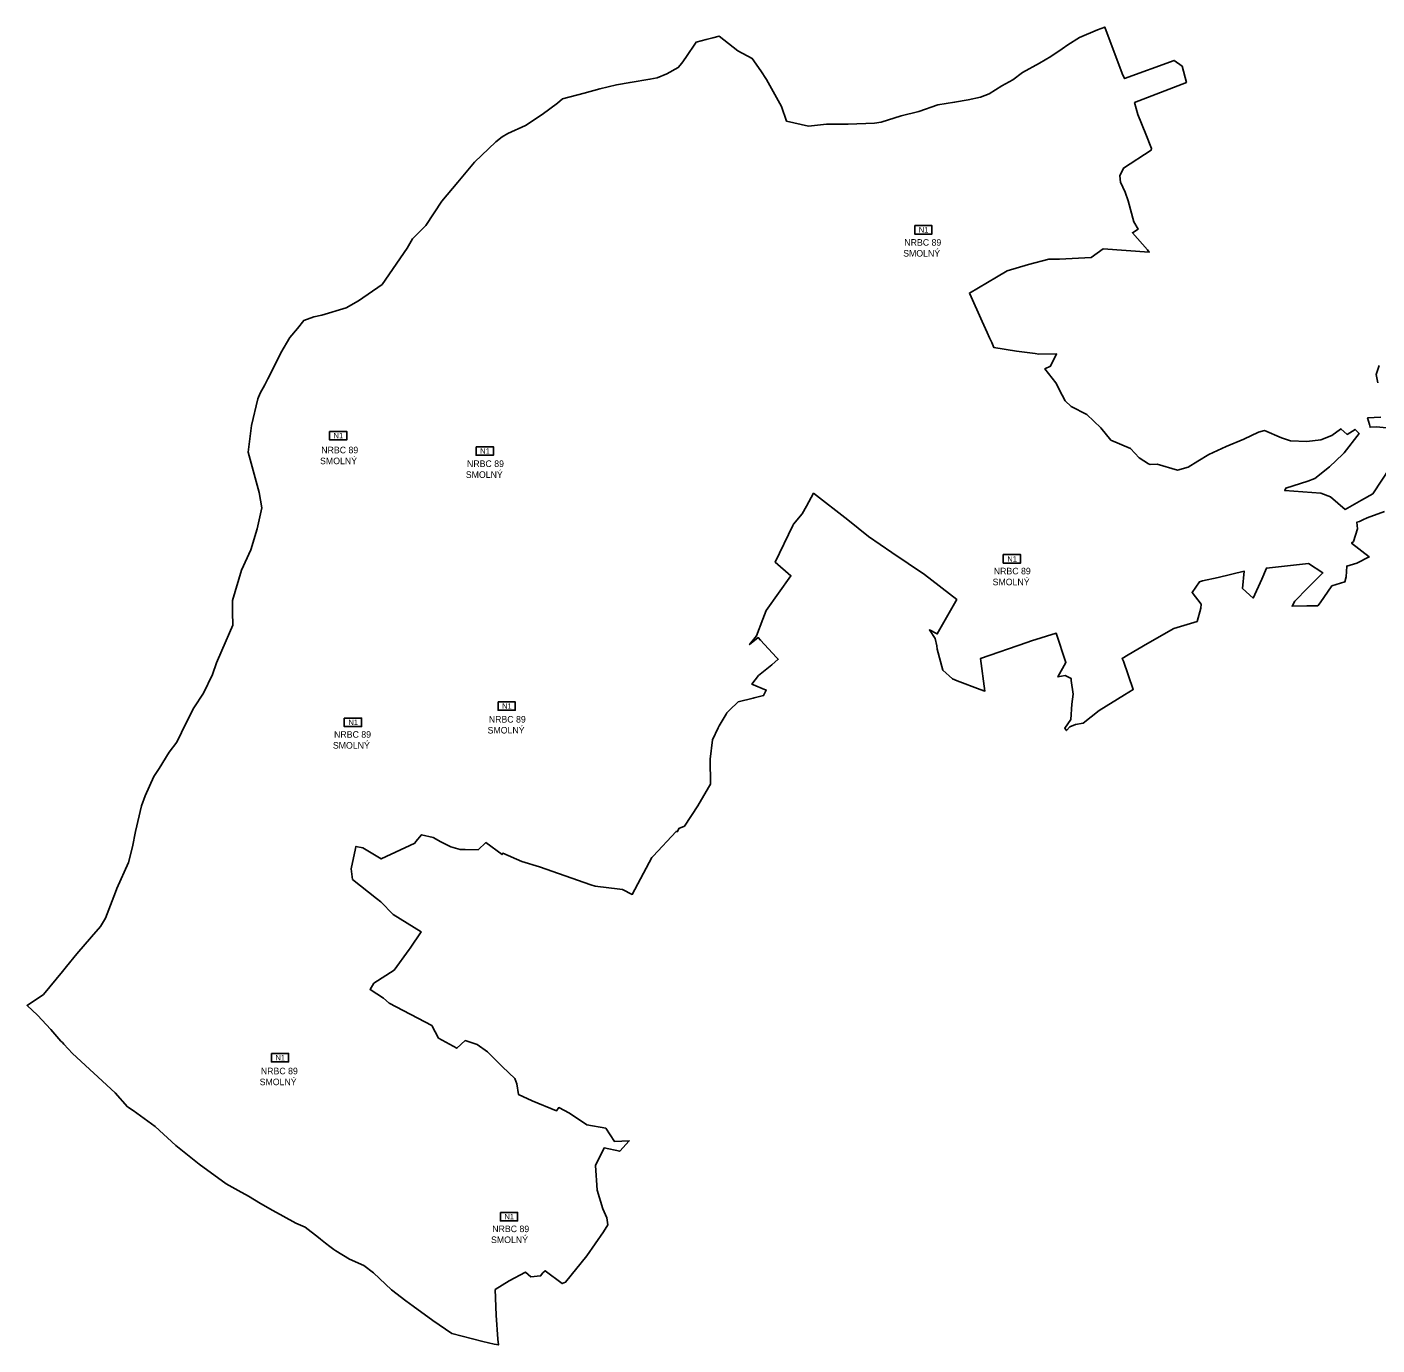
# Model space of a CAD drawing. Extents: x -546680 to -530218, y -1046521 to -1035695.
# Drawn here: x -545342 to -542866, y -1040078 to -1037661 of the extents above; entities that cross this region are included whole.
import ezdxf

# ---------------------------------------------------------------- set-up
doc = ezdxf.new("R2010")
doc.units = 0
for name, color, linetype in [('Vrstva 18', 7, 'Continuous'), ('Vrstva 3', 7, 'Continuous'), ('Vrstva 30', 7, 'Continuous'), ('Vrstva 82', 7, 'Continuous')]:
    doc.layers.add(name, color=color, linetype=linetype)

msp = doc.modelspace()

# ---------------------------------------------------------------- linework, layer by layer
at = {"layer": 'Vrstva 18'}
for points in [[(-542842.2, -1038469), (-542873.9, -1038517.1), (-542894.6, -1038529), (-542924.4, -1038545.8), (-542951.6, -1038523), (-542969.1, -1038516), (-543035.3, -1038511.4), (-543033.5, -1038506.9), (-542992.8, -1038494.1), (-542980.1, -1038489), (-542953.4, -1038468.1), (-542928.9, -1038444.7), (-542926.5, -1038442.1), (-542899, -1038406.7), (-542901.8, -1038403.8), (-542906.3, -1038399.3), (-542920.5, -1038408.5), (-542932.3, -1038398.1), (-542933.2, -1038398.7), (-542948.7, -1038410.6), (-542969.2, -1038418.6), (-542994.7, -1038421.2), (-543024.4, -1038419.9), (-543041.4, -1038414.9), (-543072.2, -1038401.5), (-543083.1, -1038404.1), (-543110.6, -1038417.1), (-543142.5, -1038430.5), (-543174.7, -1038445.5), (-543194.6, -1038457.3), (-543212.2, -1038468.2), (-543231.8, -1038473.9), (-543269.5, -1038462.9), (-543281.9, -1038463.3), (-543285, -1038462.5), (-543302.5, -1038451.6), (-543318, -1038434.2), (-543354.2, -1038418.9), (-543372.8, -1038396.3), (-543398, -1038371.7), (-543427, -1038357), (-543437.7, -1038346.5), (-543443.6, -1038336.6), (-543455.2, -1038313.8), (-543468.8, -1038296.4), (-543475, -1038287.9), (-543464.8, -1038283.2), (-543453.8, -1038260.9), (-543486.1, -1038261.1), (-543493.2, -1038260.1), (-543527.1, -1038255.8), (-543568.9, -1038248.7), (-543572.8, -1038240), (-543576.7, -1038231.1), (-543580.9, -1038221.6), (-543590, -1038201.2), (-543612.8, -1038150.6), (-543613.5, -1038149.1), (-543563.7, -1038120), (-543544.4, -1038108.5), (-543505.3, -1038096.8), (-543467.8, -1038086.7), (-543448.1, -1038086.9), (-543390.5, -1038084), (-543368.1, -1038067.8), (-543283.7, -1038074), (-543287.1, -1038070), (-543314.8, -1038038.5), (-543304.2, -1038032), (-543311.9, -1038018.7), (-543322.7, -1037980), (-543327.7, -1037964.2), (-543336.6, -1037945.7), (-543337.9, -1037933.9), (-543330.9, -1037919.8), (-543280.3, -1037887.3), (-543279.4, -1037884.1), (-543290.1, -1037857.8), (-543304.7, -1037821.8), (-543310.7, -1037799.9), (-543215.6, -1037763.1), (-543223.5, -1037733.1), (-543237.9, -1037722.6), (-543329, -1037755.8), (-543333.7, -1037746.3), (-543365.3, -1037661.2), (-543378.7, -1037666.2), (-543411.7, -1037680.3), (-543433.4, -1037694.1), (-543443.8, -1037701.3), (-543464.1, -1037715.4), (-543485.3, -1037727.6), (-543516.1, -1037744.8), (-543533.8, -1037757.8), (-543554.4, -1037769.2), (-543577.4, -1037784), (-543593.1, -1037789.8), (-543615.7, -1037794.6), (-543640.7, -1037799.2), (-543671.3, -1037804.1), (-543706.6, -1037816.2), (-543738.5, -1037824.2), (-543775.7, -1037835.8), (-543787.8, -1037837.8), (-543836.2, -1037839.6), (-543864.7, -1037839.4), (-543875.7, -1037839.6), (-543908.9, -1037842.9), (-543949.2, -1037833.6), (-543958.1, -1037807.2), (-543985.5, -1037757.2), (-543995.9, -1037741.3), (-544012, -1037718.9), (-544038.2, -1037704.7), (-544072.3, -1037678), (-544084.2, -1037681.2), (-544086.4, -1037681.7), (-544096.2, -1037684.3), (-544114.8, -1037689.2), (-544133.5, -1037717.2), (-544141, -1037727.7), (-544147.8, -1037735.5), (-544168.3, -1037747), (-544186.4, -1037754.7), (-544199.6, -1037757.1), (-544235.9, -1037762.7), (-544260.7, -1037767.4), (-544291.6, -1037774.5), (-544320.1, -1037782.7), (-544359.9, -1037792.8), (-544368.9, -1037801.1), (-544397.5, -1037821.5), (-544427.6, -1037842), (-544460.2, -1037856.7), (-544470.8, -1037862.4), (-544482.1, -1037871.9), (-544521.4, -1037909), (-544552.2, -1037945.7), (-544581.4, -1037980.8), (-544610.5, -1038025.1), (-544635, -1038049.6), (-544644.7, -1038066.8), (-544690.5, -1038133.3), (-544733.9, -1038163.3), (-544756.8, -1038176.3), (-544801.6, -1038189.5), (-544815.9, -1038192.9), (-544834.5, -1038199.3), (-544846.1, -1038214.3), (-544860, -1038230.9), (-544876.4, -1038258.7), (-544896.9, -1038299.8), (-544900.3, -1038306.4), (-544905.9, -1038317.4), (-544914.6, -1038332.8), (-544918.7, -1038343), (-544930.4, -1038392.2), (-544936.4, -1038440.7), (-544916.2, -1038514.7), (-544911.5, -1038543), (-544919.8, -1038581.8), (-544931.3, -1038620.2), (-544948.5, -1038657.6), (-544965.5, -1038713.1), (-544965.4, -1038734.1), (-544964.4, -1038758.3), (-544984.5, -1038804.7), (-544994.6, -1038827.5), (-545002, -1038848.8), (-545018.4, -1038882.7), (-545036, -1038909.9), (-545050.2, -1038937.3), (-545067.3, -1038972.6), (-545081.3, -1038991.1), (-545099.8, -1039020.9), (-545109.7, -1039035.5), (-545125.5, -1039071.5), (-545132.3, -1039089.8), (-545143.1, -1039136.7), (-545148.6, -1039164.9), (-545156.2, -1039193.4), (-545177.5, -1039241.2), (-545179.6, -1039247.7), (-545198.3, -1039295.8), (-545207.2, -1039311.1), (-545223.7, -1039329.9), (-545250.7, -1039361.1), (-545269.4, -1039384.5), (-545277.1, -1039393.5), (-545311.8, -1039435.4), (-545342.1, -1039455.5), (-545323.1, -1039473.5), (-545298.5, -1039500), (-545279.9, -1039520.9), (-545277.3, -1039523.9), (-545274.8, -1039526.7), (-545258.9, -1039543.8), (-545180.4, -1039616), (-545158.1, -1039641.5), (-545147.7, -1039648.1), (-545107.2, -1039677.4), (-545069.2, -1039712.3), (-545026.5, -1039747), (-544977.1, -1039782.6), (-544954.9, -1039795), (-544935.7, -1039805.6), (-544914, -1039818.7), (-544891.2, -1039831.7), (-544872.1, -1039842.3), (-544849.3, -1039854.8), (-544832, -1039862.5), (-544807.7, -1039881.4), (-544803.6, -1039884.5), (-544794.5, -1039891.6), (-544792.3, -1039893.2), (-544791.9, -1039893.6), (-544789, -1039895.8)], [(-542862.1, -1038281.8), (-542867.4, -1038298.6), (-542864.8, -1038313.5)], [(-542859.1, -1038376.6), (-542883.4, -1038378), (-542880, -1038390.4), (-542878.7, -1038395.2), (-542867.8, -1038394.6), (-542847.8, -1038396.5)], [(-544483.5, -1039976.4), (-544457.7, -1039961), (-544427.8, -1039945.1), (-544417.9, -1039953.1), (-544400, -1039951.6), (-544396.3, -1039946.3), (-544391.5, -1039942.2), (-544360.4, -1039965.7), (-544354.4, -1039963.2), (-544315.6, -1039914.8), (-544284.8, -1039870.8), (-544276.8, -1039858.3), (-544278.9, -1039845.1), (-544286.1, -1039828.4), (-544296.2, -1039794.7), (-544299.3, -1039749.2), (-544283.7, -1039716.8), (-544255.1, -1039723.1), (-544237.6, -1039704.1), (-544264.6, -1039705.1), (-544280.7, -1039680.6), (-544315.1, -1039674.7), (-544347.3, -1039653.1), (-544366.9, -1039643.1), (-544370.8, -1039648.7), (-544415.8, -1039630.9), (-544440.8, -1039618.8), (-544443.6, -1039599.7), (-544447.2, -1039589.8), (-544469.7, -1039568.1), (-544497.3, -1039540.7), (-544516.6, -1039527.5), (-544538.2, -1039520.2), (-544553.5, -1039534.2), (-544587.3, -1039515.6), (-544599.9, -1039492.4), (-544678.1, -1039451.3), (-544688.2, -1039442.1), (-544712.9, -1039426.7), (-544706.2, -1039415), (-544668.8, -1039391), (-544641.2, -1039353.1), (-544639.4, -1039350.6), (-544618.9, -1039320.7), (-544670.8, -1039288.9), (-544693.2, -1039265.8), (-544701.1, -1039259.5), (-544745, -1039224.6), (-544747.3, -1039205.4), (-544739.5, -1039167.7), (-544738.8, -1039163.9), (-544726.4, -1039166.3), (-544692.3, -1039187), (-544630.9, -1039158), (-544628.7, -1039155.2), (-544618.6, -1039142.6), (-544597.3, -1039147.8), (-544582.8, -1039155.3), (-544564.5, -1039164.8), (-544547.4, -1039169.8), (-544538.5, -1039169.8), (-544514.8, -1039170.1), (-544500.7, -1039156.9), (-544470.7, -1039179), (-544469.4, -1039176.4), (-544434.5, -1039191.7), (-544402.4, -1039201.7), (-544307.8, -1039234.6), (-544300.1, -1039236.8), (-544254.5, -1039242.2), (-544249.8, -1039242.8), (-544231.9, -1039251.9), (-544195.8, -1039184.6), (-544193.8, -1039181.7), (-544151.7, -1039136.6), (-544148.8, -1039136.8), (-544146.8, -1039131.4), (-544136.4, -1039126.7), (-544111.5, -1039089.6), (-544092.2, -1039056), (-544088.6, -1039049.8), (-544089.3, -1039004), (-544085, -1038968.5), (-544074.5, -1038946.6), (-544072.6, -1038942.6), (-544059.7, -1038921.2), (-544058.4, -1038918.9), (-544053.4, -1038914.1), (-544037.6, -1038898.9), (-544010.5, -1038892.2), (-544008.6, -1038891.8), (-543991.1, -1038887.5), (-543986.1, -1038877.4), (-544012.5, -1038866.5), (-544000.4, -1038850.3), (-543976.1, -1038830.8), (-543964.3, -1038820.8), (-543967.5, -1038817.5), (-543996.6, -1038785.8), (-544001, -1038781.1), (-544016.7, -1038793.7), (-544004, -1038777.8), (-543992.4, -1038747.4), (-543986.3, -1038731.5), (-543940.9, -1038667.7), (-543970, -1038642.4), (-543937.5, -1038575.3), (-543936.4, -1038573.1), (-543920.2, -1038553.8), (-543912.3, -1038539.7), (-543899.4, -1038516.3), (-543836.9, -1038564.8), (-543798.7, -1038595.6), (-543756.2, -1038625), (-543696.1, -1038665.2), (-543636.7, -1038711.2), (-543638.3, -1038714.1), (-543672.6, -1038774.4), (-543687, -1038766.8), (-543676.4, -1038782.8), (-543673.4, -1038795.9), (-543672.6, -1038802.5), (-543662.4, -1038841), (-543644.6, -1038856.9), (-543636.2, -1038860.1), (-543594, -1038876.2), (-543585.2, -1038879), (-543593, -1038819.2), (-543508.1, -1038790), (-543499.8, -1038787.2), (-543454.4, -1038773), (-543436.5, -1038826.7), (-543451.3, -1038853.2), (-543438.1, -1038850.8), (-543427, -1038856), (-543426.8, -1038859.6), (-543423.3, -1038885), (-543425.6, -1038903.1), (-543427.4, -1038931.3), (-543438.8, -1038947.2), (-543435.3, -1038951.5), (-543429.3, -1038944.8), (-543418.9, -1038940.5), (-543405, -1038938), (-543375.7, -1038914.8), (-543329.1, -1038885.9), (-543313, -1038876.3), (-543331.2, -1038824.5), (-543333.7, -1038819.2), (-543322.6, -1038812.8), (-543286.7, -1038792), (-543238.8, -1038764.6), (-543195.9, -1038751.5), (-543188.9, -1038727.1), (-543188.8, -1038720), (-543205.3, -1038698.2), (-543191.8, -1038679), (-543186.4, -1038677.2), (-543157.6, -1038670.6), (-543109.5, -1038659.2), (-543112.6, -1038690.9), (-543093.3, -1038708.7), (-543077.5, -1038673.9), (-543068.9, -1038653.5), (-542991.5, -1038645.4), (-542965.1, -1038662.3), (-542992.7, -1038690), (-543016.9, -1038714.3), (-543021.8, -1038723.6), (-542994.6, -1038722.6), (-542974.6, -1038722.7), (-542970.5, -1038717.2), (-542948.8, -1038686), (-542925.2, -1038678.8), (-542922.8, -1038669.5), (-542921.6, -1038649.8), (-542903.3, -1038644.4), (-542880.2, -1038633), (-542912.7, -1038607.6), (-542909.3, -1038604.6), (-542901.7, -1038581.6), (-542902.8, -1038569.2), (-542898.4, -1038568.4), (-542891.9, -1038565.2), (-542884.3, -1038561.6), (-542852.6, -1038549.6)], [(-544789, -1039895.8), (-544779.3, -1039903.3), (-544775.9, -1039905.9), (-544750.7, -1039920.8), (-544724.3, -1039932.5), (-544706.7, -1039945.8), (-544673.4, -1039977.3), (-544647.1, -1039997.5), (-544634, -1040007.1), (-544597.7, -1040033.6), (-544563.2, -1040057.3), (-544506.2, -1040072)], [(-544478.4, -1040067.8), (-544481.5, -1040023.9), (-544483.5, -1039976.4)], [(-544506.2, -1040072), (-544485.4, -1040076.6), (-544480.7, -1040077.7), (-544477.6, -1040078.4), (-544478.4, -1040067.8)]]:
    msp.add_lwpolyline(points, dxfattribs=at)
at = {"layer": 'Vrstva 30'}
for points in [[(-543714, -1038025.4), (-543714, -1038040.9), (-543682.3, -1038040.9), (-543682.3, -1038025.4), (-543714, -1038025.4)], [(-544787.3, -1038402.9), (-544787.3, -1038418.4), (-544755.6, -1038418.4), (-544755.6, -1038402.9), (-544787.3, -1038402.9)], [(-544518.3, -1038431.1), (-544518.3, -1038446.6), (-544486.6, -1038446.6), (-544486.6, -1038431.1), (-544518.3, -1038431.1)], [(-543551.6, -1038628.9), (-543551.6, -1038644.4), (-543519.9, -1038644.4), (-543519.9, -1038628.9), (-543551.6, -1038628.9)], [(-544478.2, -1038898.9), (-544478.2, -1038914.4), (-544446.5, -1038914.4), (-544446.5, -1038898.9), (-544478.2, -1038898.9)], [(-544760.1, -1038928.6), (-544760.1, -1038944.2), (-544728.4, -1038944.2), (-544728.4, -1038928.6), (-544760.1, -1038928.6)], [(-544893.9, -1039543.7), (-544893.9, -1039559.2), (-544862.2, -1039559.2), (-544862.2, -1039543.7), (-544893.9, -1039543.7)], [(-544473.9, -1039835.2), (-544473.9, -1039850.8), (-544442.2, -1039850.8), (-544442.2, -1039835.2), (-544473.9, -1039835.2)]]:
    msp.add_lwpolyline(points, dxfattribs=at)

# ---------------------------------------------------------------- texts
at = {"layer": 'Vrstva 3'}
for s, p in [('SMOLNÝ', (-543735.1, -1038082.3)), ('NRBC 89', (-543733, -1038062.3)), ('NRBC 89', (-544802.4, -1038443)), ('SMOLNÝ', (-544804.6, -1038463)), ('NRBC 89', (-544535.1, -1038468.1)), ('SMOLNÝ', (-544537.3, -1038488.1)), ('NRBC 89', (-543568.9, -1038665)), ('SMOLNÝ', (-543571, -1038685)), ('NRBC 89', (-544495.1, -1038936.9)), ('NRBC 89', (-544778.9, -1038964.7)), ('SMOLNÝ', (-544497.3, -1038956.9)), ('SMOLNÝ', (-544781.1, -1038984.7)), ('NRBC 89', (-544913.2, -1039581.9)), ('SMOLNÝ', (-544915.4, -1039601.9)), ('SMOLNÝ', (-544491, -1039891.4)), ('NRBC 89', (-544488.8, -1039871.4))]:
    msp.add_text(s, height=12, dxfattribs=at).set_placement(p)
at = {"layer": 'Vrstva 82'}
for p in [(-543706.5, -1038038.1), (-544779.9, -1038415.7), (-544510.9, -1038443.9), (-543544.1, -1038641.7), (-544470.7, -1038911.6), (-544752.6, -1038941.4), (-544886.4, -1039556.5), (-544466.5, -1039848)]:
    msp.add_text('N1', height=10, dxfattribs=at).set_placement(p)

doc.saveas('drawing.dxf')
